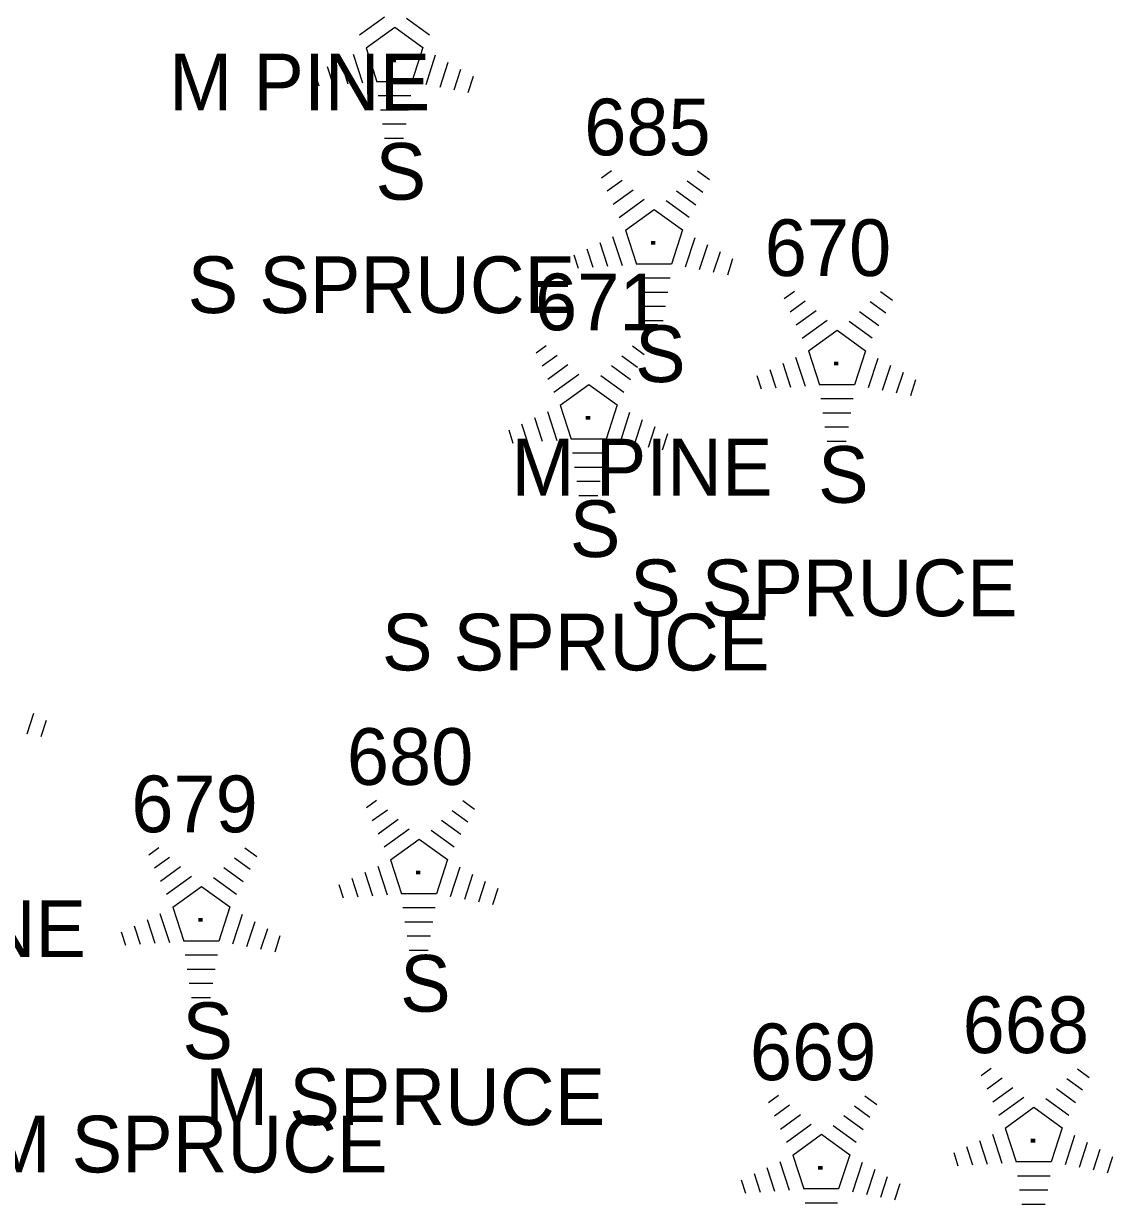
# Model space of a CAD drawing. Extents: x 1545627 to 1546562, y 571176 to 576667.
# Drawn here: x 1546288.81 to 1546327.23, y 572172.93 to 572214.59 of the extents above; entities that cross this region are included whole.
import ezdxf

# ---------------------------------------------------------------- set-up
doc = ezdxf.new("R2010")
doc.units = 0
for name, color, linetype in [('L_A', 7, 'Continuous'), ('L_C', 7, 'Continuous'), ('L_I', 7, 'Continuous'), ('LTC', 7, 'Continuous')]:
    doc.layers.add(name, color=color, linetype=linetype)

msp = doc.modelspace()

# ---------------------------------------------------------------- linework, layer by layer
at = {"layer": 'LTC'}
for p, q in [((1546300.666, 572214.187), (1546301.545, 572214.825)), ((1546302.323, 572214.779), (1546303.132, 572214.191)), ((1546300.891, 572213.732), (1546301.903, 572214.466)), ((1546301.903, 572214.466), (1546302.9, 572213.742)), ((1546300.436, 572213.513), (1546300.767, 572212.494)), ((1546300.891, 572213.732), (1546301.278, 572212.539)), ((1546302.9, 572213.742), (1546302.508, 572212.539)), ((1546299.526, 572213.08), (1546299.737, 572212.428)), ((1546299.981, 572213.297), (1546300.252, 572212.461)), ((1546303.337, 572213.471), (1546302.999, 572212.431)), ((1546303.782, 572213.22), (1546303.494, 572212.336)), ((1546299.07, 572212.863), (1546299.222, 572212.395)), ((1546304.226, 572212.97), (1546303.989, 572212.241)), ((1546304.671, 572212.72), (1546304.484, 572212.146)), ((1546302.508, 572212.539), (1546301.278, 572212.539)), ((1546302.47, 572212.039), (1546301.326, 572212.039)), ((1546302.386, 572211.539), (1546301.398, 572211.539)), ((1546302.303, 572211.039), (1546301.471, 572211.039)), ((1546302.219, 572210.539), (1546301.544, 572210.539)), ((1546309.196, 572209.149), (1546309.55, 572209.407)), ((1546312.594, 572209.39), (1546313.013, 572209.085)), ((1546309.405, 572208.684), (1546309.935, 572209.068)), ((1546312.223, 572209.041), (1546312.772, 572208.642)), ((1546309.615, 572208.218), (1546310.319, 572208.729)), ((1546311.852, 572208.693), (1546312.531, 572208.199)), ((1546309.825, 572207.752), (1546310.703, 572208.39)), ((1546311.481, 572208.345), (1546312.29, 572207.756)), ((1546310.049, 572207.297), (1546311.061, 572208.032)), ((1546311.061, 572208.032), (1546312.058, 572207.307)), ((1546310.049, 572207.297), (1546310.436, 572206.104)), ((1546312.058, 572207.307), (1546311.667, 572206.104)), ((1546309.139, 572206.862), (1546309.41, 572206.026)), ((1546309.595, 572207.078), (1546309.925, 572206.059)), ((1546312.495, 572207.036), (1546312.157, 572205.996)), ((1546308.228, 572206.429), (1546308.38, 572205.961)), ((1546308.684, 572206.645), (1546308.895, 572205.994)), ((1546312.94, 572206.786), (1546312.652, 572205.901)), ((1546313.385, 572206.536), (1546313.147, 572205.806)), ((1546311.667, 572206.104), (1546310.436, 572206.104)), ((1546313.829, 572206.285), (1546313.642, 572205.711)), ((1546311.628, 572205.604), (1546310.484, 572205.604)), ((1546315.652, 572204.891), (1546316.007, 572205.149)), ((1546311.545, 572205.104), (1546310.556, 572205.104)), ((1546315.862, 572204.426), (1546316.391, 572204.81)), ((1546318.679, 572204.783), (1546319.229, 572204.384)), ((1546319.051, 572205.132), (1546319.47, 572204.827)), ((1546311.461, 572204.604), (1546310.629, 572204.604)), ((1546316.071, 572203.96), (1546316.775, 572204.471)), ((1546318.309, 572204.435), (1546318.988, 572203.941)), ((1546311.377, 572204.104), (1546310.702, 572204.104)), ((1546316.281, 572203.494), (1546317.159, 572204.132)), ((1546317.937, 572204.087), (1546318.747, 572203.498)), ((1546316.506, 572203.039), (1546317.517, 572203.774)), ((1546317.517, 572203.774), (1546318.514, 572203.049)), ((1546306.893, 572202.978), (1546307.248, 572203.235)), ((1546310.291, 572203.218), (1546310.711, 572202.914)), ((1546307.103, 572202.512), (1546307.632, 572202.897)), ((1546309.92, 572202.87), (1546310.47, 572202.471)), ((1546316.051, 572202.82), (1546316.382, 572201.801)), ((1546316.506, 572203.039), (1546316.893, 572201.846)), ((1546318.514, 572203.049), (1546318.123, 572201.846)), ((1546318.952, 572202.778), (1546318.614, 572201.738)), ((1546307.312, 572202.047), (1546308.016, 572202.558)), ((1546309.549, 572202.522), (1546310.228, 572202.028)), ((1546315.14, 572202.387), (1546315.352, 572201.736)), ((1546315.596, 572202.604), (1546315.867, 572201.768)), ((1546319.396, 572202.528), (1546319.109, 572201.643)), ((1546319.841, 572202.278), (1546319.604, 572201.548)), ((1546307.522, 572201.581), (1546308.4, 572202.219)), ((1546307.746, 572201.126), (1546308.758, 572201.86)), ((1546308.758, 572201.86), (1546309.755, 572201.135)), ((1546309.178, 572202.173), (1546309.988, 572201.585)), ((1546314.685, 572202.171), (1546314.837, 572201.703)), ((1546318.123, 572201.846), (1546316.893, 572201.846)), ((1546320.285, 572202.027), (1546320.099, 572201.453)), ((1546307.746, 572201.126), (1546308.133, 572199.932)), ((1546309.755, 572201.135), (1546309.364, 572199.932)), ((1546318.085, 572201.346), (1546316.94, 572201.346)), ((1546306.836, 572200.69), (1546307.108, 572199.855)), ((1546307.292, 572200.907), (1546307.623, 572199.887)), ((1546310.193, 572200.865), (1546309.855, 572199.825)), ((1546310.637, 572200.614), (1546310.35, 572199.73)), ((1546318.001, 572200.846), (1546317.013, 572200.846)), ((1546305.926, 572200.257), (1546306.078, 572199.789)), ((1546306.381, 572200.474), (1546306.593, 572199.822)), ((1546311.082, 572200.364), (1546310.845, 572199.635)), ((1546317.917, 572200.346), (1546317.086, 572200.346)), ((1546309.364, 572199.932), (1546308.133, 572199.932)), ((1546311.526, 572200.114), (1546311.339, 572199.54)), ((1546317.834, 572199.846), (1546317.159, 572199.846)), ((1546309.326, 572199.432), (1546308.181, 572199.432)), ((1546309.242, 572198.932), (1546308.253, 572198.932)), ((1546309.158, 572198.432), (1546308.326, 572198.432)), ((1546309.074, 572197.932), (1546308.399, 572197.932)), ((1546289.157, 572190.252), (1546288.92, 572189.522)), ((1546289.601, 572190.001), (1546289.414, 572189.427)), ((1546300.905, 572186.94), (1546301.259, 572187.197)), ((1546301.114, 572186.474), (1546301.644, 572186.858)), ((1546303.932, 572186.832), (1546304.481, 572186.433)), ((1546304.303, 572187.18), (1546304.722, 572186.876)), ((1546301.324, 572186.008), (1546302.028, 572186.52)), ((1546303.561, 572186.483), (1546304.24, 572185.99)), ((1546301.534, 572185.543), (1546302.412, 572186.181)), ((1546303.19, 572186.135), (1546303.999, 572185.546)), ((1546301.758, 572185.088), (1546302.77, 572185.822)), ((1546302.77, 572185.822), (1546303.767, 572185.097)), ((1546293.222, 572185.269), (1546293.577, 572185.526)), ((1546293.432, 572184.803), (1546293.961, 572185.188)), ((1546296.249, 572185.161), (1546296.799, 572184.762)), ((1546296.621, 572185.509), (1546297.04, 572185.205)), ((1546293.641, 572184.338), (1546294.345, 572184.849)), ((1546295.879, 572184.813), (1546296.558, 572184.319)), ((1546301.304, 572184.868), (1546301.634, 572183.849)), ((1546301.758, 572185.088), (1546302.145, 572183.894)), ((1546303.767, 572185.097), (1546303.376, 572183.894)), ((1546304.204, 572184.826), (1546303.866, 572183.787)), ((1546293.851, 572183.872), (1546294.729, 572184.51)), ((1546295.507, 572184.464), (1546296.317, 572183.875)), ((1546300.393, 572184.436), (1546300.604, 572183.784)), ((1546300.848, 572184.652), (1546301.119, 572183.817)), ((1546304.649, 572184.576), (1546304.361, 572183.691)), ((1546305.094, 572184.326), (1546304.856, 572183.596)), ((1546294.076, 572183.417), (1546295.087, 572184.151)), ((1546295.087, 572184.151), (1546296.084, 572183.426)), ((1546299.937, 572184.219), (1546300.089, 572183.751)), ((1546305.538, 572184.076), (1546305.351, 572183.501)), ((1546303.376, 572183.894), (1546302.145, 572183.894)), ((1546293.621, 572183.198), (1546293.952, 572182.178)), ((1546294.076, 572183.417), (1546294.463, 572182.223)), ((1546296.084, 572183.426), (1546295.693, 572182.223)), ((1546296.522, 572183.155), (1546296.184, 572182.116)), ((1546303.337, 572183.394), (1546302.193, 572183.394)), ((1546292.71, 572182.765), (1546292.922, 572182.113)), ((1546293.166, 572182.981), (1546293.437, 572182.146)), ((1546296.966, 572182.905), (1546296.679, 572182.02)), ((1546297.411, 572182.655), (1546297.174, 572181.925)), ((1546303.254, 572182.894), (1546302.265, 572182.894)), ((1546292.255, 572182.548), (1546292.407, 572182.08)), ((1546297.855, 572182.405), (1546297.669, 572181.83)), ((1546303.17, 572182.394), (1546302.338, 572182.394)), ((1546295.693, 572182.223), (1546294.463, 572182.223)), ((1546303.086, 572181.894), (1546302.411, 572181.894)), ((1546295.655, 572181.723), (1546294.51, 572181.723)), ((1546295.571, 572181.223), (1546294.583, 572181.223)), ((1546295.487, 572180.723), (1546294.656, 572180.723)), ((1546295.404, 572180.223), (1546294.729, 572180.223)), ((1546322.596, 572177.479), (1546322.95, 572177.737)), ((1546325.994, 572177.72), (1546326.413, 572177.415)), ((1546322.805, 572177.014), (1546323.335, 572177.398)), ((1546325.623, 572177.371), (1546326.172, 572176.972)), ((1546323.015, 572176.548), (1546323.719, 572177.059)), ((1546325.252, 572177.023), (1546325.931, 572176.529)), ((1546315.096, 572176.523), (1546315.451, 572176.781)), ((1546315.306, 572176.058), (1546315.835, 572176.442)), ((1546318.124, 572176.415), (1546318.673, 572176.016)), ((1546318.495, 572176.763), (1546318.914, 572176.459)), ((1546323.225, 572176.082), (1546324.103, 572176.72)), ((1546324.881, 572176.675), (1546325.69, 572176.086)), ((1546315.516, 572175.592), (1546316.219, 572176.103)), ((1546317.753, 572176.067), (1546318.432, 572175.573)), ((1546323.449, 572175.627), (1546324.461, 572176.362)), ((1546324.461, 572176.362), (1546325.458, 572175.637)), ((1546315.725, 572175.126), (1546316.604, 572175.764)), ((1546317.381, 572175.718), (1546318.191, 572175.13)), ((1546323.449, 572175.627), (1546323.836, 572174.434)), ((1546325.458, 572175.637), (1546325.067, 572174.434)), ((1546315.95, 572174.671), (1546316.961, 572175.406)), ((1546316.961, 572175.406), (1546317.959, 572174.681)), ((1546322.539, 572175.192), (1546322.81, 572174.357)), ((1546322.995, 572175.408), (1546323.325, 572174.389)), ((1546325.895, 572175.366), (1546325.557, 572174.327)), ((1546321.628, 572174.759), (1546321.78, 572174.291)), ((1546322.084, 572174.975), (1546322.295, 572174.324)), ((1546326.34, 572175.116), (1546326.052, 572174.231)), ((1546326.785, 572174.866), (1546326.547, 572174.136)), ((1546315.495, 572174.452), (1546315.826, 572173.433)), ((1546315.95, 572174.671), (1546316.337, 572173.478)), ((1546317.959, 572174.681), (1546317.567, 572173.478)), ((1546318.396, 572174.41), (1546318.058, 572173.37)), ((1546325.067, 572174.434), (1546323.836, 572174.434)), ((1546327.229, 572174.615), (1546327.042, 572174.041)), ((1546314.584, 572174.019), (1546314.796, 572173.367)), ((1546315.04, 572174.236), (1546315.311, 572173.4)), ((1546318.841, 572174.159), (1546318.553, 572173.275)), ((1546319.285, 572173.909), (1546319.048, 572173.18)), ((1546325.028, 572173.934), (1546323.884, 572173.934)), ((1546314.129, 572173.802), (1546314.281, 572173.334)), ((1546319.729, 572173.659), (1546319.543, 572173.085)), ((1546317.567, 572173.478), (1546316.337, 572173.478)), ((1546324.945, 572173.434), (1546323.956, 572173.434)), ((1546317.529, 572172.978), (1546316.384, 572172.978)), ((1546324.861, 572172.934), (1546324.029, 572172.934))]:
    msp.add_line(p, q, dxfattribs=at)

# ---------------------------------------------------------------- texts
at = {"layer": 'L_A'}
for p in [(1546301.228, 572208.376), (1546310.386, 572201.941), (1546316.843, 572197.683), (1546308.084, 572195.77), (1546302.095, 572179.732), (1546294.413, 572178.061)]:
    msp.add_text('S', height=2, dxfattribs=at).set_placement(p)
at = {"layer": 'L_C'}
for s, p in [('M PINE', (1546293.943, 572211.527)), ('S SPRUCE', (1546294.598, 572204.376)), ('M PINE', (1546306.024, 572197.941)), ('S SPRUCE', (1546310.213, 572193.683)), ('S SPRUCE', (1546301.454, 572191.77)), ('M PINE', (1546281.796, 572181.657)), ('M SPRUCE', (1546295.214, 572175.732)), ('M SPRUCE', (1546287.531, 572174.061))]:
    msp.add_text(s, height=2, dxfattribs=at).set_placement(p)
at = {"layer": 'L_I'}
for s, p in [('685', (1546308.591, 572209.941)), ('670', (1546314.961, 572205.683)), ('671', (1546306.855, 572203.77)), ('680', (1546300.214, 572187.732)), ('679', (1546292.61, 572186.061)), ('668', (1546321.944, 572178.271)), ('669', (1546314.437, 572177.315))]:
    msp.add_text(s, height=2, dxfattribs=at).set_placement(p)
at = {"layer": 'LTC'}
for p in [(1546301.785, 572213.48), (1546310.943, 572207.045), (1546317.4, 572202.787), (1546308.641, 572200.874), (1546302.652, 572184.836), (1546294.97, 572183.165), (1546324.343, 572175.375), (1546316.844, 572174.419)]:
    msp.add_text('.', height=1.037, rotation=270, dxfattribs=at).set_placement(p)

doc.saveas('drawing.dxf')
